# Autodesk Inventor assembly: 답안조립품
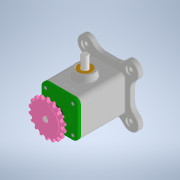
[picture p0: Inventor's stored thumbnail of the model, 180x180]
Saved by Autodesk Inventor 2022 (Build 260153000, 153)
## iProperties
Created: 2022-05
Part Number: 답안조립품
Document SubType Name: Assembly
Designer: Admin
Author: Admin
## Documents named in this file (11)
- C:\Users\Admin\Desktop\720509V1004\답안조립품.iam
- C:\Users\Admin\Desktop\720509V1004\본체.ipt
- C:\Users\Admin\Desktop\720509V1004\커버.ipt
- C:\Users\Admin\Desktop\720509V1004\베어링 6203.ipt
- C:\Users\Admin\Desktop\720509V1004\편심축.ipt
- C:\Users\Admin\Desktop\720509V1004\오일 실.ipt
- C:\Users\Admin\Desktop\720509V1004\부시.ipt
- C:\Users\Admin\Desktop\720509V1004\슬라이더.ipt
- C:\Users\Admin\Desktop\720509V1004\키 4 x 4 x 14.ipt
- C:\Users\Admin\Desktop\720509V1004\스프로킷.ipt
- C:\Users\Admin\Desktop\720509V1004\볼트 M4.ipt
